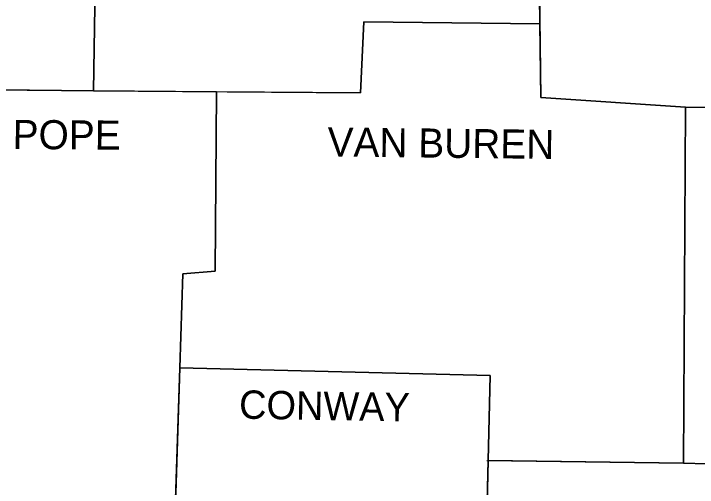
# Model space of a CAD drawing. Extents: x 1368042 to 1371376, y 380392 to 382637.
# Drawn here: x 1369518.4 to 1369729.7, y 381378.9 to 381525.2 of the extents above; entities that cross this region are included whole.
import ezdxf

# ---------------------------------------------------------------- set-up
doc = ezdxf.new("R2010")
doc.units = 0
doc.layers.add('Default', color=7, linetype='Continuous')
doc.layers.add('R_No Plot', color=7, linetype='Continuous')

msp = doc.modelspace()

# ---------------------------------------------------------------- linework, layer by layer
at = {"layer": 'Default'}
for points in [[(1369747.13, 381751.54), (1369747.56, 381700.59), (1369744.01, 381700.38), (1369744.64, 381648.39), (1369730.02, 381646.3), (1369731.27, 381632.31), (1369736.28, 381625.83), (1369735.87, 381609.34), (1369707.47, 381608.29), (1369706.42, 381582.82), (1369680.53, 381581.98), (1369679.28, 381551.08), (1369680.74, 381548.57), (1369681.36, 381499.29), (1369726.05, 381496.37), (1369725.43, 381386.32), (1369760.93, 381385.28), (1369760.93, 381273.35), (1369732.94, 381271.26), (1369730.85, 381246.62), (1369683.87, 381246.41)], [(1369542.3, 381624.53), (1369542.08, 381613.1), (1369544.79, 381612.47), (1369543.11, 381501.42)], [(1369393.81, 381502.63), (1369625.61, 381500.75), (1369626.65, 381522.68), (1369681.07, 381522.05)], [(1369581.14, 381501.11), (1369580.71, 381445.62), (1369570.69, 381444.79), (1369566.72, 381322)], [(1369726.05, 381496.37), (1369833.39, 381495.74), (1369842.58, 381500.13), (1369841.95, 381418.48), (1369835.68, 381415.76), (1369830.05, 381410.96), (1369828.17, 381409.08), (1369827.96, 381385.69), (1369746.72, 381385.69)], [(1369569.75, 381415.78), (1369665.7, 381413.47), (1369664.45, 381361.89)], [(1369664.66, 381387.16), (1369725.43, 381386.32)]]:
    msp.add_lwpolyline(points, dxfattribs=at)
at = {"layer": 'R_No Plot'}
for p, q in [((1369393.81, 381502.63), (1369543.11, 381501.42)), ((1369543.11, 381501.42), (1369491.19, 381501.84)), ((1369581.14, 381501.11), (1369543.11, 381501.42)), ((1369581.14, 381501.11), (1369580.71, 381445.62)), ((1369625.61, 381500.75), (1369581.14, 381501.11)), ((1369725.43, 381386.32), (1369726.05, 381496.37)), ((1369726.05, 381496.37), (1369831.33, 381495.75)), ((1369580.71, 381445.62), (1369570.69, 381444.79)), ((1369570.69, 381444.79), (1369569.75, 381415.78)), ((1369569.75, 381415.78), (1369566.72, 381322)), ((1369665.06, 381387.15), (1369664.45, 381361.89)), ((1369665.06, 381387.15), (1369725.43, 381386.32)), ((1369725.43, 381386.32), (1369665.06, 381387.15))]:
    msp.add_line(p, q, dxfattribs=at)
for points in [[(1369543.11, 381501.42), (1369544.79, 381612.47), (1369542.08, 381613.1), (1369542.3, 381624.53)], [(1369542.3, 381624.53), (1369542.08, 381613.1), (1369544.79, 381612.47), (1369543.11, 381501.42)], [(1369680.53, 381581.98), (1369679.28, 381551.08), (1369680.74, 381548.57), (1369681.36, 381499.29), (1369726.05, 381496.37)], [(1369681.07, 381522.05), (1369680.74, 381548.57), (1369679.28, 381551.08), (1369680.53, 381581.98)], [(1369543.11, 381501.42), (1369625.61, 381500.75), (1369626.65, 381522.68), (1369681.07, 381522.05)], [(1369681.07, 381522.05), (1369626.65, 381522.68), (1369625.61, 381500.75)], [(1369726.05, 381496.37), (1369681.36, 381499.29), (1369681.07, 381522.05)], [(1369566.72, 381322), (1369569.75, 381415.78), (1369570.69, 381444.79), (1369580.71, 381445.62), (1369581.14, 381501.11)], [(1369842.58, 381500.13), (1369833.39, 381495.74), (1369831.33, 381495.75), (1369726.05, 381496.37)], [(1369726.05, 381496.37), (1369725.43, 381386.32), (1369746.72, 381385.69)], [(1369569.75, 381415.78), (1369665.7, 381413.47), (1369665.06, 381387.15)], [(1369664.45, 381361.89), (1369665.06, 381387.15), (1369665.7, 381413.47), (1369569.75, 381415.78)], [(1369760.93, 381385.28), (1369746.72, 381385.69), (1369725.43, 381386.32)]]:
    msp.add_lwpolyline(points, dxfattribs=at)

# ---------------------------------------------------------------- texts
at = {"layer": 'Default'}
for s, height, rotation, p in [('POPE', 8.981, 359.6155, (1369518.06, 381483.42)), ('VAN BUREN', 8.981, 359.3508, (1369615.38, 381481.12)), ('CONWAY', 8.769, 359.0372, (1369588.02, 381400.1))]:
    msp.add_text(s, height=height, rotation=rotation, dxfattribs=at).set_placement(p)

doc.saveas('drawing.dxf')
